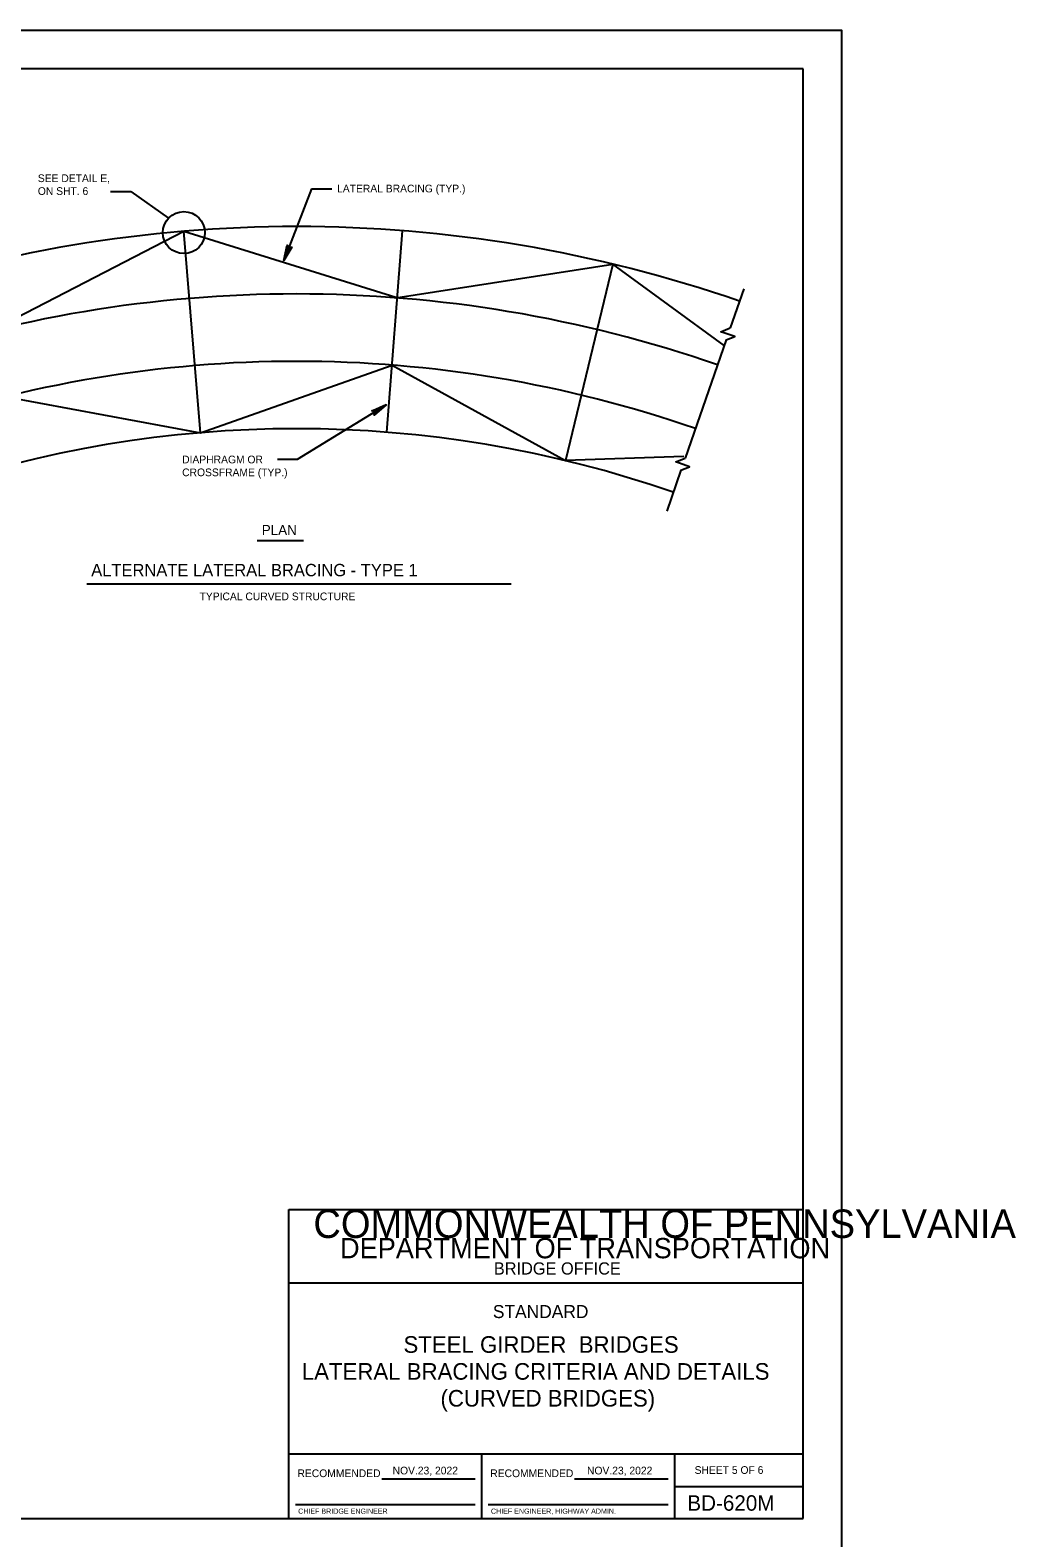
# Model space of a CAD drawing. Extents: x 30 to 2621, y -33 to 1155.
# Drawn here: x 2238 to 2621, y 569 to 1155 of the extents above; entities that cross this region are included whole.
import ezdxf

# ---------------------------------------------------------------- set-up
doc = ezdxf.new("R2010")
doc.units = 0
for name, color, linetype in [('1', 7, 'Continuous'), ('2', 7, 'Continuous'), ('PLT-BNDY', 7, 'Continuous'), ('SIGNATORY TITLES', 7, 'Continuous')]:
    doc.layers.add(name, color=color, linetype=linetype)

msp = doc.modelspace()

# ---------------------------------------------------------------- linework, layer by layer
at = {"layer": '1'}
for p, q in [((2538.5, 1140), (1752.5, 1140)), ((2538.5, 576), (2538.5, 1140)), ((2269.11, 1092.21), (2277, 1092.21)), ((2277, 1092.21), (2291.64, 1081.8)), ((2347.27, 1093.26), (2336.54, 1065.42)), ((2347.27, 1093.26), (2355.16, 1093.26)), ((2222.17, 1037.84), (2297.58, 1076.75)), ((2304.15, 998.39), (2297.58, 1076.75)), ((2297.58, 1076.75), (2380.13, 1051.14)), ((2382.61, 1076.98), (2376.46, 998.58)), ((2380.13, 1050.88), (2464.53, 1063.99)), ((2464.53, 1063.99), (2446.12, 987.54)), ((2507.76, 1032.29), (2464.53, 1063.99)), ((2515.46, 1054.31), (2510.21, 1039.17)), ((2508.57, 1034.47), (2492.61, 988.48)), ((2304.15, 998.39), (2378.29, 1024.6)), ((2378.38, 1024.78), (2446.12, 987.54)), ((2228.6, 1012.3), (2304.15, 998.39)), ((2341.9, 988.17), (2376.32, 1009.2)), ((2334.01, 988.17), (2341.9, 988.17)), ((2492.1, 989.21), (2446.12, 987.54)), ((2490.99, 983.8), (2485.48, 967.94)), ((2326.14, 956.44), (2344.24, 956.44)), ((2259.88, 939.61), (2424.9, 939.61)), ((2338.5, 696.23), (2538.5, 696.23)), ((2338.5, 576), (2338.5, 696.23)), ((2338.5, 667.75), (2538.5, 667.75)), ((2538.5, 601), (2338.5, 601)), ((2413.5, 576), (2413.5, 601)), ((2488.5, 601), (2488.5, 576)), ((2374.59, 591.5), (2411, 591.5)), ((2449.59, 591.5), (2486, 591.5)), ((2488.5, 588.5), (2538.5, 588.5)), ((2341, 581.5), (2411, 581.5)), ((2416, 581.5), (2486, 581.5)), ((1752.5, 576), (2538.5, 576))]:
    msp.add_line(p, q, dxfattribs=at)
for points in [[(2339.25, 1070.46), (2338.79, 1070.41), (2336.54, 1065.42), (2339.25, 1070.46), (2339.58, 1070.64), (2336.54, 1065.42), (2338.25, 1070.61), (2337.94, 1070.94), (2336.54, 1065.42), (2337.8, 1071.32), (2337.94, 1070.94)], [(2508.55, 1034.48), (2511.94, 1035.84), (2506.54, 1037.68), (2510.21, 1039.17)], [(2371.1, 1006.85), (2371.5, 1006.61), (2376.32, 1009.2), (2371.1, 1006.85), (2370.73, 1006.91), (2376.32, 1009.2), (2371.8, 1006.13), (2371.84, 1005.67), (2376.32, 1009.2), (2371.72, 1005.28), (2371.84, 1005.67)], [(2490.99, 983.8), (2494.38, 985.17), (2488.98, 987.01), (2492.61, 988.48)]]:
    msp.add_lwpolyline(points, dxfattribs=at)
msp.add_circle((2297.63, 1076.24), 8.17, dxfattribs=at)
for radius in [525.49, 499.28, 473.06, 446.85]:
    msp.add_arc((2341.51, 553.1), radius, 70.86038, 109.13962, dxfattribs=at)
at = {"layer": '2'}
msp.add_line((2538.5, 601), (2338.5, 601), dxfattribs=at)
at = {"layer": 'PLT-BNDY'}
msp.add_lwpolyline([(1712.5, 1155), (2553.5, 1155), (2553.5, 561), (1712.5, 561)], close=True, dxfattribs=at)

# ---------------------------------------------------------------- texts
at = {"layer": '1'}
for s, height, p in [('SEE DETAIL E,', 3, (2240.83, 1095.9)), ('ON SHT. 6', 3, (2240.83, 1090.9)), ('LATERAL BRACING (TYP.)', 3, (2357.24, 1091.89)), ('DIAPHRAGM OR', 3, (2296.96, 986.48)), ('CROSSFRAME (TYP.)', 3, (2296.96, 981.48)), ('PLAN', 3.9, (2327.95, 958.61)), ('ALTERNATE LATERAL BRACING - TYPE 1', 4.8, (2261.6, 942.57)), ('TYPICAL CURVED STRUCTURE', 3, (2303.74, 933.23)), ('COMMONWEALTH OF PENNSYLVANIA', 11.0789, (2348.03, 685.15)), ('COMMONWEALTH OF PENNSYLVANIA', 11.0789, (2348.03, 685.15)), ('DEPARTMENT OF TRANSPORTATION', 7.8962, (2358.38, 677.25)), ('DEPARTMENT OF TRANSPORTATION', 7.8962, (2358.38, 677.25)), ('BRIDGE OFFICE', 4.7495, (2418.22, 670.92)), ('STANDARD', 5.055, (2417.84, 654)), ('STEEL GIRDER  BRIDGES', 6.4601, (2383.07, 640.48)), ('LATERAL BRACING CRITERIA AND DETAILS', 6.4601, (2343.52, 630.02)), ('(CURVED BRIDGES)', 6.4601, (2397.46, 619.56)), ('RECOMMENDED', 3, (2341.83, 592.12)), ('RECOMMENDED', 3, (2416.83, 592.12)), ('SHEET 5 OF 6', 3, (2496.33, 593.38)), ('BD-620M', 6, (2493.5, 579.06))]:
    msp.add_text(s, height=height, dxfattribs=at).set_placement(p)
at = {"layer": 'SIGNATORY TITLES'}
for s, height, p in [('NOV.23, 2022', 3, (2378.84, 593.18)), ('NOV.23, 2022', 3, (2454.46, 593.18)), ('CHIEF BRIDGE ENGINEER', 2, (2342.09, 577.88)), ('CHIEF ENGINEER, HIGHWAY ADMIN.', 2, (2417.09, 577.88))]:
    msp.add_text(s, height=height, dxfattribs=at).set_placement(p)

doc.saveas('drawing.dxf')
